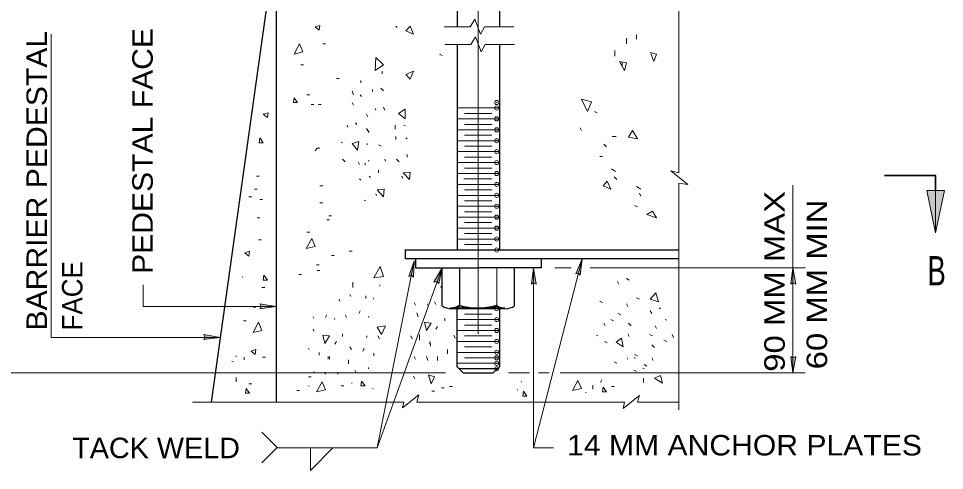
# Model space of a CAD drawing. Extents: x 312601.859 to 312602.7, y 144420.109 to 144420.704.
# Drawn here: x 312602.0589 to 312602.1946, y 144420.2595 to 144420.3257 of the extents above; entities that cross this region are included whole.
import ezdxf
from ezdxf.enums import TextEntityAlignment as Align

# ---------------------------------------------------------------- set-up
doc = ezdxf.new("R2010")
doc.units = 0
doc.header["$LTSCALE"] = 0.0012
doc.header["$PDMODE"] = 32
doc.header["$PDSIZE"] = 0.0006
doc.linetypes.add('DOT_DASHED', pattern=[7.7, 5, -1.2, 0.3, -1.2])
doc.linetypes.add('LONG_DASHED', pattern=[7.5, 6, -1.5])
for name, color, linetype, lineweight in [('1', 7, 'Continuous', 13), ('2', 7, 'Continuous', 13), ('39', 7, 'Continuous', 13)]:
    doc.layers.add(name, color=color, linetype=linetype, lineweight=lineweight)

msp = doc.modelspace()

# ---------------------------------------------------------------- hatches: boundary and pattern name
at = {"layer": '1'}
for points in [[(312602.192, 144420.3005), (312602.1933, 144420.3005), (312602.1933, 144420.2943)], [(312602.1946, 144420.3005), (312602.1933, 144420.3005), (312602.1933, 144420.2943)]]:
    msp.add_hatch(color=256, dxfattribs=at).paths.add_polyline_path(points)
at = {"layer": '39'}
for points in [[(312602.1165, 144420.2881), (312602.1161, 144420.2879), (312602.1169, 144420.2902), (312602.1168, 144420.2878)], [(312602.141, 144420.2884), (312602.1406, 144420.2883), (312602.1415, 144420.2905), (312602.1412, 144420.2881)], [(312602.1202, 144420.2872), (312602.1198, 144420.2871), (312602.121, 144420.2892), (312602.1205, 144420.2869)], [(312602.1344, 144420.287), (312602.1341, 144420.2868), (312602.1344, 144420.2892), (312602.1348, 144420.2868)], [(312602.1724, 144420.287), (312602.1721, 144420.2868), (312602.1724, 144420.2892), (312602.1728, 144420.2868)], [(312602.0945, 144420.2835), (312602.0943, 144420.2839), (312602.0967, 144420.2835), (312602.0943, 144420.2832)], [(312602.0863, 144420.279), (312602.0861, 144420.2794), (312602.0885, 144420.279), (312602.0861, 144420.2787)], [(312602.1724, 144420.276), (312602.1728, 144420.2762), (312602.1724, 144420.2738), (312602.1721, 144420.2762)]]:
    msp.add_hatch(color=256, dxfattribs=at).paths.add_polyline_path(points)

# ---------------------------------------------------------------- linework, layer by layer
at = {"layer": '1', "linetype": 'DOT_DASHED'}
msp.add_line((312602.1263, 144420.3795), (312602.1263, 144420.2731), dxfattribs=at)
at = {"layer": '1', "lineweight": 25}
for p, q in [((312602.1232, 144420.346), (312602.1232, 144420.3245)), ((312602.1294, 144420.346), (312602.1294, 144420.3245)), ((312602.0967, 144420.3373), (312602.0967, 144420.2695)), ((312602.1232, 144420.3219), (312602.1232, 144420.2918)), ((312602.1294, 144420.3219), (312602.1294, 144420.2918)), ((312602.1156, 144420.2918), (312602.1156, 144420.2905)), ((312602.1156, 144420.2918), (312602.1557, 144420.2918)), ((312602.1557, 144420.2905), (312602.1156, 144420.2905)), ((312602.1355, 144420.2905), (312602.1355, 144420.2892)), ((312602.121, 144420.2836), (312602.121, 144420.2892)), ((312602.1236, 144420.2836), (312602.1236, 144420.2892)), ((312602.1355, 144420.2892), (312602.1263, 144420.2892)), ((312602.1316, 144420.2836), (312602.1316, 144420.2892)), ((312602.1302, 144420.2832), (312602.1223, 144420.2832)), ((312602.1232, 144420.2747), (312602.1232, 144420.2832)), ((312602.1294, 144420.2832), (312602.1294, 144420.2747)), ((312602.1291, 144420.2744), (312602.1235, 144420.2744)), ((312602.1294, 144420.2747), (312602.1285, 144420.2738))]:
    msp.add_line(p, q, dxfattribs=at)
at = {"layer": '1', "linetype": 'LONG_DASHED', "lineweight": 25}
msp.add_line((312602.0872, 144420.2695), (312602.0967, 144420.3373), dxfattribs=at)
at = {"layer": '1'}
for p, q in [((312602.1557, 144420.3336), (312602.1557, 144420.3031)), ((312602.1144, 144420.3244), (312602.1142, 144420.3246)), ((312602.0637, 144420.3234), (312602.0637, 144420.279)), ((312602.1213, 144420.3245), (312602.1251, 144420.3245)), ((312602.1272, 144420.3245), (312602.1315, 144420.3245)), ((312602.1495, 144420.3227), (312602.1495, 144420.3233)), ((312602.1039, 144420.322), (312602.1035, 144420.322)), ((312602.1214, 144420.3219), (312602.1252, 144420.3219)), ((312602.1273, 144420.3219), (312602.1316, 144420.3219)), ((312602.148, 144420.322), (312602.148, 144420.3228)), ((312602.1463, 144420.3202), (312602.1463, 144420.321)), ((312602.1516, 144420.3206), (312602.152, 144420.3194)), ((312602.121, 144420.3203), (312602.1206, 144420.3205)), ((312602.1474, 144420.3187), (312602.1474, 144420.3193)), ((312602.1007, 144420.3189), (312602.1003, 144420.3189)), ((312602.1122, 144420.3176), (312602.1122, 144420.318)), ((312602.1059, 144420.3169), (312602.1055, 144420.3169)), ((312602.1091, 144420.3163), (312602.1091, 144420.3166)), ((312602.108, 144420.3145), (312602.1078, 144420.3151)), ((312602.1108, 144420.315), (312602.1108, 144420.3153)), ((312602.1124, 144420.3151), (312602.112, 144420.3155)), ((312602.1016, 144420.3145), (312602.1012, 144420.3145)), ((312602.1092, 144420.3143), (312602.109, 144420.3145)), ((312602.1022, 144420.3131), (312602.1018, 144420.3131)), ((312602.1033, 144420.3131), (312602.1029, 144420.3131)), ((312602.108, 144420.313), (312602.1078, 144420.3134)), ((312602.1113, 144420.3123), (312602.1112, 144420.3125)), ((312602.1126, 144420.3123), (312602.1124, 144420.3127)), ((312602.1294, 144420.3126), (312602.1232, 144420.3126)), ((312602.1101, 144420.3113), (312602.1099, 144420.3117)), ((312602.1283, 144420.3118), (312602.1243, 144420.3118)), ((312602.1437, 144420.3119), (312602.1433, 144420.3121)), ((312602.1072, 144420.3098), (312602.1071, 144420.3101)), ((312602.1085, 144420.3102), (312602.1083, 144420.3104)), ((312602.1141, 144420.3095), (312602.1141, 144420.3101)), ((312602.1156, 144420.31), (312602.1154, 144420.3101)), ((312602.1294, 144420.311), (312602.1232, 144420.311)), ((312602.1283, 144420.3102), (312602.1243, 144420.3102)), ((312602.1414, 144420.3093), (312602.1412, 144420.3097)), ((312602.1103, 144420.309), (312602.1099, 144420.3096)), ((312602.1142, 144420.308), (312602.1142, 144420.3084)), ((312602.1294, 144420.3094), (312602.1232, 144420.3094)), ((312602.1283, 144420.3086), (312602.1243, 144420.3086)), ((312602.1465, 144420.3084), (312602.1459, 144420.3084)), ((312602.1064, 144420.3075), (312602.1062, 144420.3076)), ((312602.11, 144420.3072), (312602.11, 144420.3074)), ((312602.1121, 144420.307), (312602.1117, 144420.3072)), ((312602.1159, 144420.3081), (312602.1157, 144420.3082)), ((312602.1294, 144420.3078), (312602.1232, 144420.3078)), ((312602.1283, 144420.307), (312602.1243, 144420.307)), ((312602.1451, 144420.3069), (312602.1447, 144420.3073)), ((312602.1159, 144420.3054), (312602.1159, 144420.3058)), ((312602.1294, 144420.3062), (312602.1232, 144420.3062)), ((312602.1068, 144420.3047), (312602.1064, 144420.3051)), ((312602.1089, 144420.3043), (312602.1087, 144420.3047)), ((312602.1097, 144420.3042), (312602.1097, 144420.3045)), ((312602.1103, 144420.3048), (312602.1102, 144420.3049)), ((312602.1127, 144420.3048), (312602.1126, 144420.3051)), ((312602.1147, 144420.3047), (312602.1143, 144420.3051)), ((312602.1294, 144420.3046), (312602.1232, 144420.3046)), ((312602.1283, 144420.3054), (312602.1243, 144420.3054)), ((312602.1445, 144420.3055), (312602.1441, 144420.3055)), ((312602.1117, 144420.3031), (312602.1117, 144420.3035)), ((312602.1294, 144420.303), (312602.1232, 144420.303)), ((312602.1283, 144420.3038), (312602.1243, 144420.3038)), ((312602.1464, 144420.3033), (312602.1458, 144420.3037)), ((312602.1545, 144420.3034), (312602.157, 144420.3014)), ((312602.1545, 144420.3034), (312602.1557, 144420.3031)), ((312602.0942, 144420.3026), (312602.0938, 144420.3026)), ((312602.1091, 144420.302), (312602.1089, 144420.3022)), ((312602.1105, 144420.3024), (312602.1103, 144420.3026)), ((312602.1152, 144420.3023), (312602.1151, 144420.3026)), ((312602.1282, 144420.3022), (312602.1242, 144420.3022)), ((312602.1283, 144420.3022), (312602.1243, 144420.3022)), ((312602.1466, 144420.3021), (312602.1462, 144420.3025)), ((312602.1557, 144420.3016), (312602.1557, 144420.2684)), ((312602.1557, 144420.3016), (312602.157, 144420.3014)), ((312602.0939, 144420.3007), (312602.0935, 144420.3007)), ((312602.1035, 144420.3012), (312602.1031, 144420.3012)), ((312602.1294, 144420.3014), (312602.1232, 144420.3014)), ((312602.1283, 144420.3006), (312602.1243, 144420.3006)), ((312602.1501, 144420.3007), (312602.1495, 144420.3011)), ((312602.0931, 144420.2996), (312602.0927, 144420.2996)), ((312602.0947, 144420.2992), (312602.0943, 144420.2992)), ((312602.1098, 144420.299), (312602.1096, 144420.2991)), ((312602.1114, 144420.2998), (312602.1113, 144420.3)), ((312602.1294, 144420.2998), (312602.1232, 144420.2998)), ((312602.1283, 144420.299), (312602.1243, 144420.299)), ((312602.1501, 144420.2997), (312602.1499, 144420.3001)), ((312602.1035, 144420.2987), (312602.1031, 144420.2987)), ((312602.1294, 144420.2982), (312602.1232, 144420.2982)), ((312602.1496, 144420.2981), (312602.1492, 144420.2983)), ((312602.0943, 144420.2965), (312602.0939, 144420.2965)), ((312602.1045, 144420.2962), (312602.1041, 144420.2962)), ((312602.1048, 144420.2968), (312602.1044, 144420.2968)), ((312602.1294, 144420.2966), (312602.1232, 144420.2966)), ((312602.1283, 144420.2974), (312602.1243, 144420.2974)), ((312602.1294, 144420.295), (312602.1232, 144420.295)), ((312602.1283, 144420.2958), (312602.1243, 144420.2958)), ((312602.1016, 144420.2944), (312602.1012, 144420.2944)), ((312602.1294, 144420.2934), (312602.1232, 144420.2934)), ((312602.1283, 144420.2942), (312602.1243, 144420.2942)), ((312602.0945, 144420.2933), (312602.0941, 144420.2933)), ((312602.1283, 144420.2926), (312602.1243, 144420.2926)), ((312602.1052, 144420.291), (312602.1048, 144420.291)), ((312602.1078, 144420.2916), (312602.1074, 144420.2916)), ((312602.1294, 144420.2918), (312602.1232, 144420.2918)), ((312602.103, 144420.2896), (312602.1026, 144420.2896)), ((312602.1344, 144420.2628), (312602.1415, 144420.2905)), ((312602.1004, 144420.2882), (312602.1, 144420.2882)), ((312602.1031, 144420.2888), (312602.1027, 144420.2888)), ((312602.121, 144420.2892), (312602.1115, 144420.2628)), ((312602.129, 144420.2836), (312602.129, 144420.2892)), ((312602.1344, 144420.2892), (312602.1344, 144420.2628)), ((312602.1399, 144420.2892), (312602.1375, 144420.2892)), ((312602.1742, 144420.2892), (312602.1427, 144420.2892)), ((312602.0917, 144420.2878), (312602.0918, 144420.2878)), ((312602.1079, 144420.2863), (312602.1079, 144420.2871)), ((312602.1118, 144420.2865), (312602.1119, 144420.2867)), ((312602.1469, 144420.2868), (312602.1467, 144420.2872)), ((312602.1484, 144420.2874), (312602.148, 144420.2876)), ((312602.095, 144420.2863), (312602.0946, 144420.2863)), ((312602.1076, 144420.285), (312602.1075, 144420.2853)), ((312602.1209, 144420.2862), (312602.1208, 144420.2865)), ((312602.106, 144420.2843), (312602.1059, 144420.2846)), ((312602.1098, 144420.2847), (312602.1098, 144420.2851)), ((312602.111, 144420.2846), (312602.1109, 144420.2848)), ((312602.1171, 144420.2837), (312602.1169, 144420.2841)), ((312602.1188, 144420.2837), (312602.1189, 144420.2839)), ((312602.1201, 144420.2838), (312602.1199, 144420.2842)), ((312602.1445, 144420.2841), (312602.1441, 144420.2843)), ((312602.1482, 144420.2835), (312602.148, 144420.2839)), ((312602.1499, 144420.2846), (312602.1495, 144420.2848)), ((312602.0937, 144420.2834), (312602.0933, 144420.2834)), ((312602.1088, 144420.2825), (312602.109, 144420.2829)), ((312602.1175, 144420.282), (312602.1173, 144420.2826)), ((312602.1301, 144420.2833), (312602.1222, 144420.2833)), ((312602.1232, 144420.2832), (312602.1232, 144420.2749)), ((312602.1517, 144420.2825), (312602.1515, 144420.2829)), ((312602.153, 144420.2832), (312602.1528, 144420.2833)), ((312602.0923, 144420.2814), (312602.0919, 144420.2814)), ((312602.1022, 144420.2818), (312602.1021, 144420.282)), ((312602.1039, 144420.2819), (312602.1041, 144420.2823)), ((312602.1053, 144420.2816), (312602.1052, 144420.2818)), ((312602.107, 144420.2819), (312602.1068, 144420.2823)), ((312602.1103, 144420.2819), (312602.1102, 144420.2821)), ((312602.1214, 144420.2814), (312602.1214, 144420.2818)), ((312602.1294, 144420.2816), (312602.1232, 144420.2816)), ((312602.1283, 144420.2824), (312602.1243, 144420.2824)), ((312602.1461, 144420.2814), (312602.1457, 144420.2816)), ((312602.1472, 144420.2823), (312602.1468, 144420.2825)), ((312602.1539, 144420.2815), (312602.1537, 144420.2816)), ((312602.1022, 144420.2799), (312602.1021, 144420.2802)), ((312602.1201, 144420.2802), (312602.1203, 144420.2806)), ((312602.1294, 144420.28), (312602.1232, 144420.28)), ((312602.1283, 144420.2808), (312602.1243, 144420.2808)), ((312602.1449, 144420.2807), (312602.1447, 144420.2811)), ((312602.1487, 144420.2807), (312602.1483, 144420.2811)), ((312602.1524, 144420.2803), (312602.1522, 144420.2807)), ((312602.0637, 144420.279), (312602.0885, 144420.279)), ((312602.1064, 144420.2791), (312602.1064, 144420.2795)), ((312602.1099, 144420.279), (312602.11, 144420.2792)), ((312602.1118, 144420.2788), (312602.1116, 144420.2792)), ((312602.1166, 144420.2788), (312602.1164, 144420.2792)), ((312602.1177, 144420.2786), (312602.1177, 144420.2794)), ((312602.1229, 144420.2789), (312602.1227, 144420.2793)), ((312602.1283, 144420.2792), (312602.1243, 144420.2792)), ((312602.1438, 144420.2792), (312602.1436, 144420.2793)), ((312602.1484, 144420.2791), (312602.1482, 144420.2795)), ((312602.1518, 144420.2792), (312602.1514, 144420.2794)), ((312602.1539, 144420.2784), (312602.1535, 144420.2786)), ((312602.1549, 144420.279), (312602.1547, 144420.2794)), ((312602.1015, 144420.2772), (312602.1014, 144420.2774)), ((312602.1053, 144420.278), (312602.1055, 144420.2784)), ((312602.1077, 144420.2772), (312602.1075, 144420.2776)), ((312602.1094, 144420.277), (312602.1096, 144420.2774)), ((312602.1192, 144420.278), (312602.1192, 144420.2784)), ((312602.1193, 144420.2777), (312602.1193, 144420.2781)), ((312602.1218, 144420.2766), (312602.1218, 144420.2772)), ((312602.1294, 144420.2784), (312602.1232, 144420.2784)), ((312602.1283, 144420.2776), (312602.1243, 144420.2776)), ((312602.1452, 144420.2782), (312602.1448, 144420.2784)), ((312602.1521, 144420.2775), (312602.1517, 144420.2779)), ((312602.0909, 144420.2762), (312602.0907, 144420.2763)), ((312602.092, 144420.2757), (312602.092, 144420.2761)), ((312602.0951, 144420.2761), (312602.0947, 144420.2761)), ((312602.103, 144420.2764), (312602.103, 144420.2768)), ((312602.1043, 144420.2758), (312602.1043, 144420.2762)), ((312602.1045, 144420.2758), (312602.1045, 144420.2762)), ((312602.111, 144420.2763), (312602.111, 144420.2767)), ((312602.1171, 144420.2758), (312602.1169, 144420.2762)), ((312602.1189, 144420.2756), (312602.1187, 144420.2762)), ((312602.1203, 144420.2756), (312602.1203, 144420.2762)), ((312602.1294, 144420.2768), (312602.1232, 144420.2768)), ((312602.1294, 144420.276), (312602.1243, 144420.276)), ((312602.1482, 144420.2758), (312602.1481, 144420.276)), ((312602.1496, 144420.2763), (312602.1492, 144420.2765)), ((312602.1493, 144420.2759), (312602.1492, 144420.2761)), ((312602.1519, 144420.2756), (312602.1517, 144420.276)), ((312602.0904, 144420.2754), (312602.0902, 144420.2755)), ((312602.1073, 144420.2751), (312602.1073, 144420.2757)), ((312602.1102, 144420.2744), (312602.1102, 144420.2746)), ((312602.1294, 144420.2752), (312602.1232, 144420.2752)), ((312602.1466, 144420.2752), (312602.1462, 144420.2754)), ((312602.1506, 144420.2744), (312602.1504, 144420.2745)), ((312602.151, 144420.2748), (312602.1506, 144420.275)), ((312602.0517, 144420.2738), (312602.1215, 144420.2738)), ((312602.0908, 144420.2725), (312602.0908, 144420.2731)), ((312602.1018, 144420.2732), (312602.1014, 144420.2732)), ((312602.1023, 144420.2738), (312602.1022, 144420.274)), ((312602.1039, 144420.2736), (312602.1038, 144420.2739)), ((312602.1057, 144420.2736), (312602.1057, 144420.2739)), ((312602.1084, 144420.2738), (312602.1082, 144420.2742)), ((312602.117, 144420.2729), (312602.1168, 144420.2733)), ((312602.1192, 144420.2729), (312602.119, 144420.2735)), ((312602.1241, 144420.2738), (312602.1284, 144420.2738)), ((312602.1242, 144420.2738), (312602.128, 144420.2738)), ((312602.1307, 144420.2738), (312602.1338, 144420.2738)), ((312602.1351, 144420.2738), (312602.1367, 144420.2738)), ((312602.1383, 144420.2738), (312602.1742, 144420.2738)), ((312602.1495, 144420.274), (312602.1491, 144420.2742)), ((312602.0931, 144420.2722), (312602.0927, 144420.2722)), ((312602.1014, 144420.2719), (312602.1015, 144420.2719)), ((312602.1066, 144420.2719), (312602.1062, 144420.2719)), ((312602.1077, 144420.2723), (312602.1078, 144420.2723)), ((312602.1225, 144420.2718), (312602.1221, 144420.2718)), ((312602.1326, 144420.2725), (312602.1327, 144420.2725)), ((312602.1431, 144420.2714), (312602.1431, 144420.272)), ((312602.1442, 144420.2724), (312602.1444, 144420.2728)), ((312602.1462, 144420.2718), (312602.1458, 144420.2718)), ((312602.1505, 144420.2724), (312602.1505, 144420.273)), ((312602.1001, 144420.2712), (312602.0997, 144420.2712)), ((312602.1108, 144420.2715), (312602.1109, 144420.2715)), ((312602.1176, 144420.2706), (312602.1152, 144420.2687)), ((312602.1176, 144420.2706), (312602.1173, 144420.2695)), ((312602.1199, 144420.2711), (312602.1195, 144420.2711)), ((312602.1213, 144420.2716), (312602.1209, 144420.2716)), ((312602.132, 144420.2713), (312602.1321, 144420.2713)), ((312602.142, 144420.2709), (312602.1421, 144420.2709)), ((312602.1499, 144420.2705), (312602.1475, 144420.2686)), ((312602.1499, 144420.2705), (312602.1496, 144420.2695)), ((312602.0844, 144420.2695), (312602.1154, 144420.2695)), ((312602.1154, 144420.2695), (312602.1152, 144420.2687)), ((312602.1173, 144420.2695), (312602.1477, 144420.2695)), ((312602.1477, 144420.2695), (312602.1475, 144420.2686)), ((312602.1496, 144420.2695), (312602.1557, 144420.2695)), ((312602.0968, 144420.2628), (312602.1115, 144420.2628)), ((312602.1017, 144420.2628), (312602.1017, 144420.2595)), ((312602.1344, 144420.2628), (312602.1373, 144420.2628))]:
    msp.add_line(p, q, dxfattribs=at)
for points in [[(312602.1515, 144420.3207), (312602.1524, 144420.3205), (312602.152, 144420.3194)], [(312602.1031, 144420.3067), (312602.1027, 144420.3067), (312602.1024, 144420.3063)], [(312602.1724, 144420.3013), (312602.1724, 144420.2892), (312602.1724, 144420.2738)], [(312602.0772, 144420.2867), (312602.0772, 144420.2835), (312602.0967, 144420.2835)]]:
    msp.add_lwpolyline(points, dxfattribs=at)
for points in [[(312602.1113, 144420.32), (312602.1124, 144420.3189), (312602.1112, 144420.3181)], [(312602.147, 144420.3194), (312602.148, 144420.3192), (312602.1477, 144420.3181)], [(312602.1414, 144420.3139), (312602.1429, 144420.3135), (312602.1423, 144420.3121)], [(312602.1146, 144420.3118), (312602.1156, 144420.3124), (312602.1156, 144420.311)], [(312602.1483, 144420.3083), (312602.1489, 144420.3093), (312602.1496, 144420.3081)], [(312602.1078, 144420.3074), (312602.1088, 144420.3077), (312602.1086, 144420.3064)], [(312602.1153, 144420.3031), (312602.1163, 144420.3032), (312602.1162, 144420.3021)], [(312602.1446, 144420.3012), (312602.1452, 144420.3019), (312602.1457, 144420.3007)], [(312602.1115, 144420.3006), (312602.1125, 144420.3007), (312602.1124, 144420.2996)], [(312602.192, 144420.3005), (312602.1933, 144420.3005), (312602.1933, 144420.2943)], [(312602.1946, 144420.3005), (312602.1933, 144420.3005), (312602.1933, 144420.2943)], [(312602.151, 144420.297), (312602.1518, 144420.2975), (312602.1524, 144420.2965)], [(312602.1119, 144420.2894), (312602.1124, 144420.2879), (312602.111, 144420.2877)], [(312602.1515, 144420.2846), (312602.1523, 144420.2855), (312602.1527, 144420.2842)], [(312602.1184, 144420.2812), (312602.1194, 144420.2811), (312602.1187, 144420.28)], [(312602.1115, 144420.2805), (312602.1127, 144420.2807), (312602.1121, 144420.2794)], [(312602.1035, 144420.2793), (312602.1045, 144420.2792), (312602.1038, 144420.2781)], [(312602.1465, 144420.2783), (312602.1473, 144420.2789), (312602.1475, 144420.2776)], [(312602.119, 144420.2735), (312602.1199, 144420.2732), (312602.1194, 144420.2722)], [(312602.1521, 144420.273), (312602.153, 144420.2734), (312602.1533, 144420.2723)]]:
    msp.add_lwpolyline(points, close=True, dxfattribs=at)
at = {"layer": '1', "lineweight": 35}
msp.add_lwpolyline([(312602.1933, 144420.3005), (312602.1933, 144420.3027), (312602.1858, 144420.3027)], dxfattribs=at)
at = {"layer": '1', "lineweight": 25}
for points in [[(312602.1171, 144420.2905), (312602.1171, 144420.2892), (312602.1263, 144420.2892)], [(312602.1232, 144420.2747), (312602.1241, 144420.2738), (312602.1285, 144420.2738)]]:
    msp.add_lwpolyline(points, dxfattribs=at)
for centre, radius, start, end in [((312602.1223, 144420.2855), 0.0023, 235.58261, 304.37164), ((312602.1263, 144420.292512), 0.0093125, 253.14606, 286.87109), ((312602.1262, 144420.2964), 0.0132004, 282.23769, 282.24633), ((312602.1303, 144420.2855), 0.0023, 235.69352, 304.41739)]:
    msp.add_arc(centre, radius, start, end, dxfattribs=at)
at = {"layer": '1'}
for centre, radius, start, end in [((312602.1222, 144420.2856), 0.0023, 270, 304.37164), ((312602.1262, 144420.292612), 0.0093125, 253.14606, 286.87109), ((312602.1302, 144420.2856), 0.0023, 235.69352, 270), ((312602.1344, 144420.2964), 0.0132004, 257.75367, 257.76231)]:
    msp.add_arc(centre, radius, start, end, dxfattribs=at)
for p in [(312602.129, 144420.3134), (312602.129, 144420.3126), (312602.129, 144420.311), (312602.129, 144420.3094), (312602.129, 144420.3078), (312602.129, 144420.3062), (312602.129, 144420.3046), (312602.129, 144420.303), (312602.129, 144420.3014), (312602.129, 144420.2998), (312602.129, 144420.2982), (312602.129, 144420.2966), (312602.129, 144420.295), (312602.129, 144420.2934), (312602.129, 144420.2918), (312602.129, 144420.2832), (312602.129, 144420.2816), (312602.129, 144420.28), (312602.129, 144420.2784), (312602.129, 144420.2768), (312602.129, 144420.276), (312602.129, 144420.2752), (312602.129, 144420.2744)]:
    msp.add_point(p, dxfattribs=at)
at = {"layer": '2'}
for p, q in [((312602.1115, 144420.2628), (312602.1168, 144420.2897)), ((312602.0946, 144420.2651), (312602.0969, 144420.2628)), ((312602.0946, 144420.2606), (312602.0968, 144420.2628)), ((312602.1017, 144420.2595), (312602.105, 144420.2628))]:
    msp.add_line(p, q, dxfattribs=at)
for points in [[(312602.1031, 144420.3247), (312602.1024, 144420.3245), (312602.103, 144420.324)], [(312602.1163, 144420.3246), (312602.1157, 144420.3239), (312602.1168, 144420.3234)], [(312602.1001, 144420.322), (312602.0993, 144420.3205), (312602.1006, 144420.3208)], [(312602.1163, 144420.3168), (312602.1157, 144420.3175), (312602.1168, 144420.318)], [(312602.0993, 144420.3141), (312602.0992, 144420.3134), (312602.0998, 144420.3134)], [(312602.0955, 144420.3119), (312602.0948, 144420.3117), (312602.0954, 144420.3112)], [(312602.0943, 144420.3082), (312602.0942, 144420.3075), (312602.0948, 144420.3075)], [(312602.1019, 144420.2935), (312602.1011, 144420.292), (312602.1024, 144420.2923)], [(312602.0928, 144420.2916), (312602.0921, 144420.2914), (312602.0927, 144420.2909)], [(312602.0949, 144420.2881), (312602.0948, 144420.2874), (312602.0954, 144420.2874)], [(312602.0941, 144420.2812), (312602.0933, 144420.2797), (312602.0946, 144420.28)], [(312602.0937, 144420.2772), (312602.093, 144420.277), (312602.0936, 144420.2765)], [(312602.1034, 144420.2725), (312602.1026, 144420.271), (312602.1039, 144420.2713)], [(312602.1092, 144420.2726), (312602.1091, 144420.2719), (312602.1097, 144420.2719)], [(312602.1409, 144420.2727), (312602.1401, 144420.2712), (312602.1414, 144420.2715)], [(312602.1446, 144420.2717), (312602.1445, 144420.271), (312602.1451, 144420.271)], [(312602.0923, 144420.2715), (312602.0922, 144420.2708), (312602.0928, 144420.2708)], [(312602.1329, 144420.2711), (312602.1328, 144420.2704), (312602.1334, 144420.2704)]]:
    msp.add_lwpolyline(points, close=True, dxfattribs=at)
for points in [[(312602.1251, 144420.3245), (312602.1258, 144420.3256), (312602.1266, 144420.3234), (312602.1272, 144420.3245)], [(312602.1252, 144420.3219), (312602.1259, 144420.323), (312602.1267, 144420.3208), (312602.1273, 144420.3219)]]:
    msp.add_lwpolyline(points, dxfattribs=at)
at = {"layer": '39'}
for points in [[(312602.1165, 144420.2881), (312602.1161, 144420.2879), (312602.1169, 144420.2902), (312602.1168, 144420.2878)], [(312602.141, 144420.2884), (312602.1406, 144420.2883), (312602.1415, 144420.2905), (312602.1412, 144420.2881)], [(312602.1202, 144420.2872), (312602.1198, 144420.2871), (312602.121, 144420.2892), (312602.1205, 144420.2869)], [(312602.1344, 144420.287), (312602.1341, 144420.2868), (312602.1344, 144420.2892), (312602.1348, 144420.2868)], [(312602.1724, 144420.287), (312602.1721, 144420.2868), (312602.1724, 144420.2892), (312602.1728, 144420.2868)], [(312602.0945, 144420.2835), (312602.0943, 144420.2839), (312602.0967, 144420.2835), (312602.0943, 144420.2832)], [(312602.0863, 144420.279), (312602.0861, 144420.2794), (312602.0885, 144420.279), (312602.0861, 144420.2787)], [(312602.1724, 144420.276), (312602.1728, 144420.2762), (312602.1724, 144420.2738), (312602.1721, 144420.2762)]]:
    msp.add_lwpolyline(points, close=True, dxfattribs=at)

# ---------------------------------------------------------------- texts
at = {"layer": '2'}
for s, width, p in [('BARRIER PEDESTAL', 1.1, (312602.0631, 144420.28)), ('FACE', 0.95, (312602.0683, 144420.28))]:
    msp.add_text(s, height=0.003, rotation=90, dxfattribs=dict(at, width=width)).set_placement(p)
for s, height, width, p in [('PEDESTAL FACE', 0.002998, 1.1, (312602.0786, 144420.3063)), ('90 MM MAX', 0.003, 1.2, (312602.1712, 144420.2872)), ('60 MM MIN', 0.003, 1.2, (312602.1774, 144420.28675))]:
    msp.add_text(s, height=height, rotation=90, dxfattribs=dict(at, width=width)).set_placement(p, align=Align.CENTER)
for s, height, width, p in [('B', 0.0043, 0.7, (312602.19345, 144420.2866)), ('14 MM ANCHOR PLATES', 0.003, 1.1, (312602.1653, 144420.2617))]:
    msp.add_text(s, height=height, dxfattribs=dict(at, width=width)).set_placement(p, align=Align.CENTER)
at = {"layer": '2', "width": 1.05}
msp.add_text('TACK WELD', height=0.003, dxfattribs=at).set_placement((312602.0668, 144420.2613))

doc.saveas('drawing.dxf')
